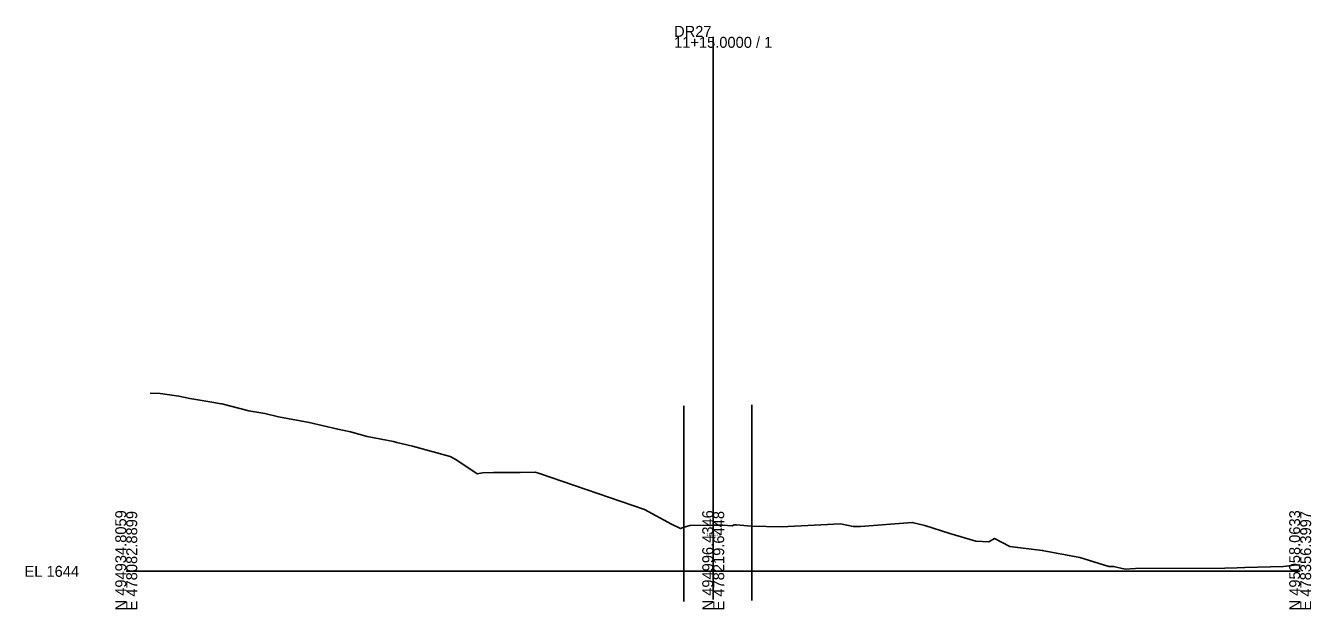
# Model space of a CAD drawing. Extents: x -26 to 478410, y -18 to 495058.
# Drawn here: x -25.7 to 302.8, y 1990.3 to 2139.3 of the extents above; entities that cross this region are included whole.
import ezdxf

# ---------------------------------------------------------------- set-up
doc = ezdxf.new("R2010")
doc.units = 0
for name, color, linetype in [('Exist Cross Section Cell', 7, 'Continuous'), ('Exist XS Center Line Elevation Label', 7, 'Continuous'), ('Exist XS Ground Line', 7, 'Continuous'), ('Scratch_Level_4', 7, 'Continuous')]:
    doc.layers.add(name, color=color, linetype=linetype)

msp = doc.modelspace()

# ---------------------------------------------------------------- linework, layer by layer
at = {"layer": 'Exist Cross Section Cell'}
for p, q in [((150, 2000), (150, 2136.49)), ((0, 2000), (150, 2000)), ((150, 2000), (300, 2000))]:
    msp.add_line(p, q, dxfattribs=at)
at = {"layer": 'Exist XS Ground Line'}
msp.add_lwpolyline([(6.14, 2045.5), (8.66, 2045.42), (13.45, 2044.69), (16.22, 2044.13), (22.36, 2043.15), (23.78, 2042.83), (24.42, 2042.73), (31.34, 2041.02), (35.39, 2040.3), (38.91, 2039.48), (46.71, 2038.04), (54.03, 2036.26), (57.33, 2035.65), (61.59, 2034.47), (68.3, 2033.16), (69.16, 2032.93), (73.16, 2031.96), (82.81, 2029.29), (84.25, 2028.58), (89.67, 2024.89), (91.01, 2025.11), (93.81, 2025.26), (100.68, 2025.27), (104.48, 2025.33), (105.64, 2024.96), (132.4, 2015.81), (139.32, 2012.08), (141.68, 2010.91), (142.31, 2011.22), (143.99, 2011.7), (150, 2011.76), (152.46, 2011.78), (154.84, 2011.64), (155.35, 2011.83), (155.93, 2011.9), (159.67, 2011.56), (167.49, 2011.39), (182.53, 2012.12), (185.78, 2011.47), (187.63, 2011.44), (200.88, 2012.48), (204.1, 2011.69), (210.43, 2009.67), (217.12, 2007.69), (220.41, 2007.57), (221.89, 2008.36), (225.81, 2006.34), (234.07, 2005.34), (243.72, 2003.49), (251.06, 2001.26), (252.33, 2001.26), (255.26, 2000.57), (257.9, 2000.72), (280.72, 2000.77), (283.89, 2000.89), (285.83, 2000.98), (295.7, 2001.27), (298.5, 2001.56), (300, 2001.68)], dxfattribs=at)
at = {"layer": 'Scratch_Level_4'}
for p, q in [((142.51, 2042.28), (142.51, 1992.28)), ((150, 2042.76), (150, 1992.76)), ((159.83, 2042.55), (159.83, 1992.55))]:
    msp.add_line(p, q, dxfattribs=at)

# ---------------------------------------------------------------- texts
at = {"layer": 'Exist Cross Section Cell'}
for s, p in [('DR27', (140, 2136.49)), ('11+15.0000 / 1', (140, 2133.69)), ('EL 1644', (-26, 1998.6))]:
    msp.add_text(s, height=2.8, dxfattribs=at).set_placement(p)
for s, p in [('N 494934.8059', (0, 1990)), ('E 478082.8899', (2.8, 1990)), ('N 494996.4346', (150, 1990)), ('E 478219.6448', (152.8, 1990)), ('N 495058.0633', (300, 1990)), ('E 478356.3997', (302.8, 1990))]:
    msp.add_text(s, height=2.8, rotation=90, dxfattribs=at).set_placement(p)
at = {"layer": 'Exist XS Center Line Elevation Label'}
msp.add_text('1655.76', height=0.75, dxfattribs=at).set_placement((148.26, 2009.01))

doc.saveas('drawing.dxf')
